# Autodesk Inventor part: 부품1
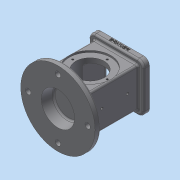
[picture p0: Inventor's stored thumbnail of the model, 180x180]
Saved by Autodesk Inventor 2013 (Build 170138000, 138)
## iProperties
Created: 2018-10
Part Number: 부품1
Material: 일반
Document SubType Name: Modeling
Designer: Administrator
Density: 1 g/cm^3
Author: Administrator
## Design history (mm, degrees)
sketch "스케치1"
  geometry: L1 (37, 33)-(-37, 33); L2 (-37, 33)-(-37, -33); L3 (-37, -33)-(37, -33); L4 (37, -33)-(37, 33); L5 (37, 33)-(-37, -33); L6 (-37, 33)-(37, -33); 1 further point
  constraints: 12 end point, 2 midpoint, 2 parallel, 1 horizontal, 1 perpendicular
  dimensions: "d0" = 74 distance of L3.end L2.end; "d1" = 66 distance of L2.end L1.end
extrude "돌출1" new body sketch "스케치1" stored distance "d2" = 108; taper "d3" = 0 deg
sketch "스케치2"
  geometry: L1 (-37, -33)-(37, -33) reference; L2 (37, -33)-(37, 33) reference; L3 (37, 33)-(-37, 33) reference; L4 (-37, 33)-(-37, -33) reference; L5 (-46, -41)-(46, -41); L6 (46, -41)-(46, 41); L7 (46, 41)-(-46, 41); L8 (-46, 41)-(-46, -41); L9 (-46, -41)-(46, 41); L10 (46, -41)-(-46, 41); 1 further point
  constraints: 12 end point, 2 midpoint, 2 parallel, 1 horizontal, 1 perpendicular
  dimensions: "d4" = 92 distance of L7.end L6.end; "d5" = 82 distance of L6.end L5.end
extrude "돌출2" join sketch "스케치2" distance "d6" = 10; taper "d7" = 0 deg
sketch "스케치3"
  geometry: L1 (37, 33)-(-37, 33) reference; L2 (-37, 33)-(-37, -33) reference; L3 (-37, -33)-(37, -33) reference; L4 (37, -33)-(37, 33) reference; C1 r 62.5 at (0, 0); 1 further point
  constraints: 1 centre point, 1 coincident
  dimensions: "d8" = 125 diameter of C1
extrude "돌출3" join sketch "스케치3" distance "d9" = 10; taper "d10" = 0 deg
node "작업 평면1"
sketch "스케치4"
  geometry: C1 r 35 at (0, 0); 1 further point
  constraints: 1 centre point, 1 coincident
  dimensions: "d12" = 70 diameter of C1
extrude "돌출4" cut sketch "스케치4" distance "d13" = 3; taper "d14" = 0 deg
sketch "스케치5"
  geometry: C1 r 35 at (0, 0) reference; C2 r 24 at (0, 0)
  constraints: 1 centre point, 1 coincident
  dimensions: "d15" = 48 diameter of C2
extrude "돌출5" cut sketch "스케치5" stored distance "d16" = 3; taper "d17" = 0 deg
sketch "스케치6" dims "d18" = 58
  geometry: C1 r 35 at (0, 0) reference; 2 further points
  constraints: 2 vertical alignment, 1 coincident, 2 other
hole "구멍1" sketch "스케치6" at (0, 29) diameter "d19" = 3.242; stored, may be unused: countersink angle "d23" = 90 deg, drill point angle "d25" = 118 deg; dims "d20" = 4, "d21" = 4, "d22" = 2, "d24" = 6
sketch "스케치7"
  geometry: L1 (-26, -26)-(26, -26); L2 (26, -26)-(26, 26); L3 (26, 26)-(-26, 26); L4 (-26, 26)-(-26, -26); L5 (-26, -26)-(26, 26); L6 (26, -26)-(-26, 26); 1 further point
  constraints: 12 end point, 2 midpoint, 2 parallel, 1 horizontal, 1 perpendicular
  dimensions: "d29" = 52 distance of L3.end L2.end; "d30" = 52 distance of L2.end L1.end
extrude "돌출6" cut sketch "스케치7" distance "d31" = 8; taper "d32" = 0 deg
sketch "스케치8"
  geometry: L1 (-22, -22)-(22, -22); L2 (22, -22)-(22, 22); L3 (22, 22)-(-22, 22); L4 (-22, 22)-(-22, -22); L5 (-22, -22)-(22, 22); L6 (22, -22)-(-22, 22); 1 further point
  constraints: 12 end point, 2 midpoint, 2 parallel, 1 horizontal, 1 perpendicular
  dimensions: "d33" = 44 distance of L3.end L2.end; "d34" = 44 distance of L2.end L1.end
extrude "돌출7" cut sketch "스케치8" distance "d35" = 74; taper "d36" = 0 deg
sketch "스케치9"
  geometry: L1 (-46, 44)-(-46, 54) reference; L2 (-46, 54)-(-26, 54) reference; L3 (-26, 54)-(-26, 46) reference; L4 (-26, 46)-(-22, 46) reference; L5 (-22, 46)-(-22, 9.592) reference; L6 (-22, -9.592)-(-22, -28) reference; L7 (-22, -28)-(22, -28) reference; L8 (22, -28)-(22, -9.592) reference; L9 (22, 9.592)-(22, 46) reference; L10 (22, 46)-(26, 46) reference; L11 (26, 46)-(26, 54) reference; L12 (26, 54)-(46, 54) reference; L13 (46, 54)-(46, 44) reference; L14 (46, 44)-(37, 44) reference; L15 (37, 44)-(37, -44) reference; L16 (37, -44)-(62.5, -44) reference; L17 (62.5, -44)-(62.5, -54) reference; L18 (62.5, -54)-(-62.5, -54) reference; L19 (-62.5, -54)-(-62.5, -44) reference; L20 (-62.5, -44)-(-37, -44) reference; L21 (-37, -44)-(-37, 44) reference; L22 (-37, 44)-(-46, 44) reference; L23 (-28, -54)-(-24.826, -36); L24 (-24.826, -36)-(0, -36); L25 (0, -36)-(0, -54); L26 (-28, -54)-(0, -54); A1 r 24 centre (0, 0) between (-22, 9.592) and (-22, -9.592) reference; A2 r 24 centre (0, 0) between (22, -9.592) and (22, 9.592) reference; 1 further point
  constraints: 8 end point, 1 collinear, 1 midpoint, 1 parallel, 1 point on line
  dimensions: "d37" = 18 distance between parallel lines of L24 L26; "d39" = 80 deg angle of L26 L23; "d41" = 18 distance of L24.end L25.end; "d42" = 56 diameter of L23.start L25
revolve "회전1" sketch "스케치9" stored, may be unused: angle "d43" = 90 deg
sketch "스케치10"
  geometry: 5 further points
  dimensions: "d44" = 72 distance of point (36, 31) point (-36, 31); "d46" = 62 distance of point (36, -31) point (36, 31); "d47" = 36 horizontal distance of point (36, 31) point (0, 0); "d48" = 31 vertical distance of point (36, 31) point (0, 0); "d49" = 36 horizontal distance of point (0, 0) point (-36, 31); "d50" = 31 vertical distance of point (36, -31) point (0, 0); "d51" = 72 distance of point (36, -31) point (-36, -31); "d52" = 36 horizontal distance of point (0, 0) point (-36, -31)
hole "구멍2" sketch "스케치10" at (-36, 31), (36, 31), (36, -31), (-36, -31) diameter "d53" = 3.242; stored, may be unused: countersink angle "d57" = 90 deg, drill point angle "d59" = 118 deg; dims "d54" = 4, "d55" = 4, "d56" = 2, "d58" = 6
sketch "스케치11" dims "d60" = 100
  geometry: C1 r 62.5 at (0, 0) reference; 2 further points
  constraints: 2 vertical alignment, 1 coincident, 2 other
hole "구멍3" sketch "스케치11" at (0, 50) diameter "d61" = 9; stored, may be unused: countersink angle "d65" = 90 deg, drill point angle "d67" = 118 deg; dims "d62" = 4, "d63" = 4, "d64" = 2, "d66" = 6
fillet "모깎기1" dims "d71" = 10
node "작업 평면2"
sketch "스케치12"
  geometry: L1 (36, 44)-(-36, 44) reference; L2 (-36, 54)-(-36, 44) reference; L3 (-36, 54)-(36, 54) reference; L4 (36, 54)-(36, 44) reference; L5 (-47.173, -54)-(-47.173, -44) reference; L6 (-47.173, -44)-(47.173, -44) reference; L7 (47.173, -44)-(47.173, -54) reference; L8 (47.173, -54)-(-47.173, -54) reference; L9 (-46, 54)-(-46, 44) reference; 2 further points
  constraints: 1 vertical alignment, 1 other
  dimensions: "d74" = 4 distance from line of L3 point (0, 50)
feature "엠보싱1" sketch "스케치12" dims "d0" = 74, "d1" = 66, "d75" = 0.5, "d76" = 0
fillet "모깎기2" dims "d77" = 3
fillet "모깎기3" dims "d78" = 3
chamfer "모따기1" distance "d79" = 1; stored, may be unused: second distance "d80" = 2, angle "d81" = 45 deg
fillet "모깎기4" dims "d82" = 3
node "작업 평면3"
sketch "스케치14"
  geometry: L1 (-54, -62.5)-(-54, 62.5) reference; 3 further points
  constraints: 2 horizontal alignment
  dimensions: "d84" = 37 distance from line of L1 point (-17, 0); "d85" = 43 distance of point (26, 0) point (-17, 0)
hole "구멍4" sketch "스케치14" at (26, 0), (-17, 0) diameter "d86" = 4.134; stored, may be unused: countersink angle "d90" = 90 deg, drill point angle "d92" = 118 deg; dims "d87" = 20, "d88" = 4, "d89" = 2, "d91" = 20
node "솔리드1"
mirror "대칭1"
pattern_circular "원형 패턴1" dims angle "d27" = 360 deg
mirror "대칭2"
pattern_circular "원형 패턴2" dims angle "d69" = 360 deg
node "절단 모서리 투영1"
node "절단 모서리 투영2"
other parameters: "d11" = 33, "d72" = 41, "d83" = 37
